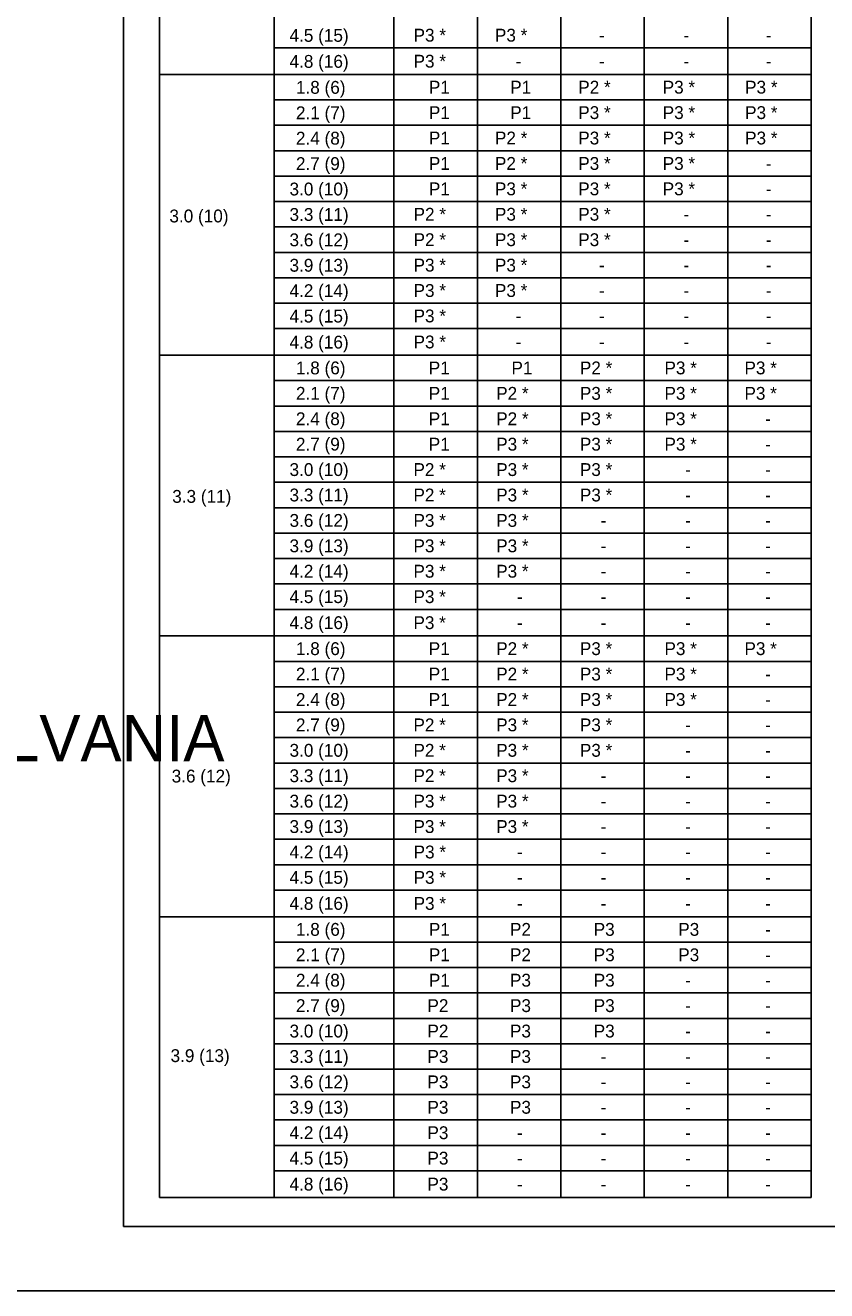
# Model space of a CAD drawing. Extents: x -1958 to 628, y -879 to 309.
# Drawn here: x -1100.4 to -913, y -878.6 to -582.8 of the extents above; entities that cross this region are included whole.
import ezdxf

# ---------------------------------------------------------------- set-up
doc = ezdxf.new("R2010")
doc.units = 0
for name, color, linetype in [('1', 7, 'Continuous'), ('2', 7, 'Continuous'), ('30', 7, 'Continuous'), ('PLT-BNDY', 7, 'Continuous')]:
    doc.layers.add(name, color=color, linetype=linetype)

msp = doc.modelspace()

# ---------------------------------------------------------------- linework, layer by layer
at = {"layer": '1'}
for p, q in [((-1077.39, -299.56), (-1077.39, -863.56)), ((-1069, -856.76), (-1069, -331.88)), ((-916.65, -856.76), (-916.65, -331.88)), ((-1042.2, -665.87), (-916.65, -665.87)), ((-1042.2, -671.81), (-916.65, -671.81)), ((-1042.2, -677.75), (-916.65, -677.75)), ((-1042.2, -683.69), (-916.65, -683.69)), ((-1042.2, -689.63), (-916.65, -689.63)), ((-1042.2, -695.57), (-916.65, -695.57)), ((-1042.2, -701.51), (-916.65, -701.51)), ((-1042.2, -707.45), (-916.65, -707.45)), ((-1042.2, -713.39), (-916.65, -713.39)), ((-1042.2, -719.33), (-916.65, -719.33)), ((-1069, -725.54), (-916.65, -725.54)), ((-1042.2, -731.48), (-916.65, -731.48)), ((-1042.2, -737.42), (-916.65, -737.42)), ((-1042.2, -743.36), (-916.65, -743.36)), ((-1042.2, -749.3), (-916.65, -749.3)), ((-940.21, -749.3), (-916.65, -749.3)), ((-1042.2, -755.24), (-916.65, -755.24)), ((-1042.2, -761.18), (-916.65, -761.18)), ((-1042.2, -767.12), (-916.65, -767.12)), ((-940.21, -767.12), (-916.65, -767.12)), ((-1042.2, -773.06), (-916.65, -773.06)), ((-1042.2, -779), (-916.65, -779)), ((-1042.2, -784.94), (-916.65, -784.94)), ((-1069, -791.15), (-916.65, -791.15)), ((-1042.2, -797.09), (-916.65, -797.09)), ((-1042.2, -803.03), (-916.65, -803.03)), ((-1042.2, -808.97), (-916.65, -808.97)), ((-1042.2, -814.91), (-916.65, -814.91)), ((-1042.2, -820.85), (-916.65, -820.85)), ((-1042.2, -826.79), (-916.65, -826.79)), ((-1042.2, -832.73), (-916.65, -832.73)), ((-1042.2, -838.67), (-916.65, -838.67)), ((-1042.2, -844.61), (-916.65, -844.61)), ((-1042.2, -850.55), (-916.65, -850.55)), ((-1069, -856.76), (-916.65, -856.76)), ((-291.39, -863.56), (-1077.39, -863.56)), ((-1077.39, -863.56), (-491.39, -863.56))]:
    msp.add_line(p, q, dxfattribs=at)
at = {"layer": '2'}
for p, q in [((-1042.2, -856.76), (-1042.2, -331.88)), ((-1014.19, -856.76), (-1014.19, -331.88)), ((-994.68, -856.76), (-994.68, -331.88)), ((-975.17, -856.76), (-975.17, -331.88)), ((-955.67, -856.76), (-955.67, -331.88)), ((-936.16, -856.76), (-936.16, -331.88)), ((-1042.2, -588.11), (-916.65, -588.11)), ((-1069, -594.32), (-916.65, -594.32)), ((-1042.2, -600.26), (-916.65, -600.26)), ((-1042.2, -606.2), (-916.65, -606.2)), ((-1042.2, -612.14), (-916.65, -612.14)), ((-1042.2, -618.08), (-916.65, -618.08)), ((-1042.2, -624.02), (-916.65, -624.02)), ((-1042.2, -629.96), (-916.65, -629.96)), ((-1042.2, -635.9), (-916.65, -635.9)), ((-1042.2, -641.84), (-916.65, -641.84)), ((-1042.2, -647.78), (-916.65, -647.78)), ((-1042.2, -653.72), (-916.65, -653.72)), ((-975.85, -653.72), (-940.21, -653.72)), ((-1069, -659.93), (-916.65, -659.93))]:
    msp.add_line(p, q, dxfattribs=at)
at = {"layer": 'PLT-BNDY'}
msp.add_lwpolyline([(-1117.39, -284.56), (-276.39, -284.56), (-276.39, -878.56), (-1117.39, -878.56)], close=True, dxfattribs=at)

# ---------------------------------------------------------------- texts
at = {"layer": '1'}
for s, height, p in [('2.1 (7)', 3, (-1037.1, -670.34)), ('P1', 3, (-1006.05, -670.34)), ('P2 *', 3, (-990.29, -670.34)), ('P3 *', 3, (-970.72, -670.34)), ('P3 *', 3, (-950.95, -670.34)), ('P3 *', 3, (-932.25, -670.34)), ('2.4 (8)', 3, (-1037.1, -676.28)), ('P1', 3, (-1006.05, -676.28)), ('P2 *', 3, (-990.29, -676.28)), ('P3 *', 3, (-970.72, -676.28)), ('P3 *', 3, (-950.95, -676.28)), ('-', 3, (-927.4, -676.28)), ('2.7 (9)', 3, (-1037.1, -682.22)), ('P1', 3, (-1006.05, -682.22)), ('P3 *', 3, (-990.29, -682.22)), ('P3 *', 3, (-970.72, -682.22)), ('P3 *', 3, (-950.95, -682.22)), ('-', 3, (-927.4, -682.22)), ('3.0 (10)', 3, (-1038.6, -688.16)), ('P2 *', 3, (-1009.63, -688.16)), ('P3 *', 3, (-990.29, -688.16)), ('P3 *', 3, (-970.72, -688.16)), ('-', 3, (-946.1, -688.16)), ('-', 3, (-927.4, -688.16)), ('3.3 (11)', 3, (-1038.6, -694.1)), ('P2 *', 3, (-1009.63, -694.1)), ('P3 *', 3, (-990.29, -694.1)), ('P3 *', 3, (-970.72, -694.1)), ('-', 3, (-946.1, -694.1)), ('-', 3, (-927.4, -694.1)), ('3.6 (12)', 3, (-1038.6, -700.04)), ('P3 *', 3, (-1009.63, -700.04)), ('P3 *', 3, (-990.29, -700.04)), ('-', 3, (-965.87, -700.04)), ('-', 3, (-946.1, -700.04)), ('-', 3, (-927.4, -700.04)), ('3.9 (13)', 3, (-1038.6, -705.98)), ('P3 *', 3, (-1009.63, -705.98)), ('P3 *', 3, (-990.29, -705.98)), ('-', 3, (-965.87, -705.98)), ('-', 3, (-946.1, -705.98)), ('-', 3, (-927.4, -705.98)), ('4.2 (14)', 3, (-1038.6, -711.92)), ('P3 *', 3, (-1009.63, -711.92)), ('P3 *', 3, (-990.29, -711.92)), ('-', 3, (-965.87, -711.92)), ('-', 3, (-946.1, -711.92)), ('-', 3, (-927.4, -711.92)), ('4.5 (15)', 3, (-1038.6, -717.86)), ('P3 *', 3, (-1009.63, -717.86)), ('-', 3, (-985.44, -717.86)), ('-', 3, (-965.87, -717.86)), ('-', 3, (-946.1, -717.86)), ('-', 3, (-927.4, -717.86)), ('4.8 (16)', 3, (-1038.6, -723.94)), ('P3 *', 3, (-1009.63, -723.94)), ('-', 3, (-985.44, -723.94)), ('-', 3, (-965.87, -723.94)), ('-', 3, (-946.1, -723.94)), ('-', 3, (-927.4, -723.94)), ('1.8 (6)', 3, (-1037.1, -730.01)), ('P1', 3, (-1006.05, -730.01)), ('P2 *', 3, (-990.29, -730.01)), ('P3 *', 3, (-970.72, -730.01)), ('P3 *', 3, (-950.95, -730.01)), ('P3 *', 3, (-932.25, -730.01)), ('2.1 (7)', 3, (-1037.1, -735.95)), ('P1', 3, (-1006.05, -735.95)), ('P2 *', 3, (-990.29, -735.95)), ('P3 *', 3, (-970.72, -735.95)), ('P3 *', 3, (-950.95, -735.95)), ('-', 3, (-927.4, -735.95)), ('2.4 (8)', 3, (-1037.1, -741.89)), ('P1', 3, (-1006.05, -741.89)), ('P2 *', 3, (-990.29, -741.89)), ('P3 *', 3, (-970.72, -741.89)), ('P3 *', 3, (-950.95, -741.89)), ('-', 3, (-927.4, -741.89)), ('COMMONWEALTH OF PENNSYLVANIA', 10.7827, (-1319.79, -754.83)), ('2.7 (9)', 3, (-1037.1, -747.83)), ('P2 *', 3, (-1009.63, -747.83)), ('P3 *', 3, (-990.29, -747.83)), ('P3 *', 3, (-970.72, -747.83)), ('-', 3, (-946.1, -747.83)), ('-', 3, (-927.4, -747.83)), ('3.0 (10)', 3, (-1038.6, -753.77)), ('P2 *', 3, (-1009.63, -753.77)), ('P3 *', 3, (-990.29, -753.77)), ('P3 *', 3, (-970.72, -753.77)), ('-', 3, (-946.1, -753.77)), ('-', 3, (-927.4, -753.77)), ('3.6 (12)', 3, (-1066.15, -759.79)), ('3.3 (11)', 3, (-1038.6, -759.71)), ('P2 *', 3, (-1009.63, -759.71)), ('P3 *', 3, (-990.29, -759.71)), ('-', 3, (-965.87, -759.71)), ('-', 3, (-946.1, -759.71)), ('-', 3, (-927.4, -759.71)), ('3.6 (12)', 3, (-1038.6, -765.65)), ('P3 *', 3, (-1009.63, -765.65)), ('P3 *', 3, (-990.29, -765.65)), ('-', 3, (-965.87, -765.65)), ('-', 3, (-946.1, -765.65)), ('-', 3, (-927.4, -765.65)), ('3.9 (13)', 3, (-1038.6, -771.59)), ('P3 *', 3, (-1009.63, -771.59)), ('P3 *', 3, (-990.29, -771.59)), ('-', 3, (-965.87, -771.59)), ('-', 3, (-946.1, -771.59)), ('-', 3, (-927.4, -771.59)), ('4.2 (14)', 3, (-1038.6, -777.53)), ('P3 *', 3, (-1009.59, -777.53)), ('-', 3, (-985.44, -777.53)), ('-', 3, (-965.87, -777.53)), ('-', 3, (-946.1, -777.53)), ('-', 3, (-927.4, -777.53)), ('4.5 (15)', 3, (-1038.6, -783.47)), ('P3 *', 3, (-1009.59, -783.47)), ('-', 3, (-985.44, -783.47)), ('-', 3, (-965.87, -783.47)), ('-', 3, (-946.1, -783.47)), ('-', 3, (-927.4, -783.47)), ('4.8 (16)', 3, (-1038.6, -789.55)), ('P3 *', 3, (-1009.59, -789.55)), ('-', 3, (-985.44, -789.55)), ('-', 3, (-965.87, -789.55)), ('-', 3, (-946.1, -789.55)), ('-', 3, (-927.4, -789.55)), ('1.8 (6)', 3, (-1037.1, -795.62)), ('P1', 3, (-1006.02, -795.62)), ('P2', 3, (-987.06, -795.62)), ('P3', 3, (-967.49, -795.62)), ('P3', 3, (-947.72, -795.62)), ('-', 3, (-927.4, -795.62)), ('2.1 (7)', 3, (-1037.1, -801.56)), ('P1', 3, (-1006.02, -801.56)), ('P2', 3, (-987.06, -801.56)), ('P3', 3, (-967.49, -801.56)), ('P3', 3, (-947.72, -801.56)), ('-', 3, (-927.4, -801.56)), ('2.4 (8)', 3, (-1037.1, -807.5)), ('P1', 3, (-1006.02, -807.5)), ('P3', 3, (-987.06, -807.5)), ('P3', 3, (-967.49, -807.5)), ('-', 3, (-946.1, -807.5)), ('-', 3, (-927.4, -807.5)), ('2.7 (9)', 3, (-1037.1, -813.44)), ('P2', 3, (-1006.36, -813.44)), ('P3', 3, (-987.06, -813.44)), ('P3', 3, (-967.49, -813.44)), ('-', 3, (-946.1, -813.44)), ('-', 3, (-927.4, -813.44)), ('3.0 (10)', 3, (-1038.6, -819.38)), ('P2', 3, (-1006.36, -819.38)), ('P3', 3, (-987.06, -819.38)), ('P3', 3, (-967.49, -819.38)), ('-', 3, (-946.1, -819.38)), ('-', 3, (-927.4, -819.38)), ('3.9 (13)', 3, (-1066.41, -825.13)), ('3.3 (11)', 3, (-1038.6, -825.32)), ('P3', 3, (-1006.36, -825.32)), ('P3', 3, (-987.06, -825.32)), ('-', 3, (-965.87, -825.32)), ('-', 3, (-946.1, -825.32)), ('-', 3, (-927.4, -825.32)), ('3.6 (12)', 3, (-1038.6, -831.26)), ('P3', 3, (-1006.36, -831.26)), ('P3', 3, (-987.06, -831.26)), ('-', 3, (-965.87, -831.26)), ('-', 3, (-946.1, -831.26)), ('-', 3, (-927.4, -831.26)), ('3.9 (13)', 3, (-1038.6, -837.2)), ('P3', 3, (-1006.36, -837.2)), ('P3', 3, (-987.06, -837.2)), ('-', 3, (-965.88, -837.2)), ('-', 3, (-946.1, -837.2)), ('-', 3, (-927.4, -837.2)), ('4.2 (14)', 3, (-1038.6, -843.14)), ('P3', 3, (-1006.36, -843.14)), ('-', 3, (-985.44, -843.14)), ('-', 3, (-965.88, -843.14)), ('-', 3, (-946.1, -843.14)), ('-', 3, (-927.4, -843.14)), ('4.5 (15)', 3, (-1038.6, -849.08)), ('P3', 3, (-1006.36, -849.08)), ('-', 3, (-985.44, -849.08)), ('-', 3, (-965.88, -849.08)), ('-', 3, (-946.1, -849.08)), ('-', 3, (-927.4, -849.08)), ('4.8 (16)', 3, (-1038.6, -855.16)), ('P3', 3, (-1006.36, -855.16)), ('-', 3, (-985.44, -855.16)), ('-', 3, (-965.88, -855.16)), ('-', 3, (-946.1, -855.16)), ('-', 3, (-927.4, -855.16))]:
    msp.add_text(s, height=height, dxfattribs=at).set_placement(p)
at = {"layer": '2'}
for s, p in [('4.5 (15)', (-1038.6, -586.68)), ('P3 *', (-1009.6, -586.64)), ('P3 *', (-990.58, -586.64)), ('-', (-966.25, -586.64)), ('-', (-946.51, -586.64)), ('-', (-927.25, -586.64)), ('4.8 (16)', (-1038.6, -592.76)), ('P3 *', (-1009.6, -592.72)), ('-', (-985.73, -592.72)), ('-', (-966.25, -592.72)), ('-', (-946.51, -592.72)), ('-', (-927.25, -592.72)), ('1.8 (6)', (-1037.1, -598.83)), ('P1', (-1006.02, -598.79)), ('P1', (-987.01, -598.79)), ('P2 *', (-971.1, -598.79)), ('P3 *', (-951.36, -598.79)), ('P3 *', (-932.1, -598.79)), ('2.1 (7)', (-1037.1, -604.77)), ('P1', (-1006.02, -604.73)), ('P1', (-987.01, -604.73)), ('P3 *', (-971.1, -604.73)), ('P3 *', (-951.36, -604.73)), ('P3 *', (-932.1, -604.73)), ('2.4 (8)', (-1037.1, -610.71)), ('P1', (-1006.02, -610.67)), ('P2 *', (-990.58, -610.67)), ('P3 *', (-971.1, -610.67)), ('P3 *', (-951.36, -610.67)), ('P3 *', (-932.1, -610.67)), ('2.7 (9)', (-1037.1, -616.65)), ('P1', (-1006.02, -616.61)), ('P2 *', (-990.58, -616.61)), ('P3 *', (-971.1, -616.61)), ('P3 *', (-951.36, -616.61)), ('-', (-927.25, -616.61)), ('3.0 (10)', (-1038.6, -622.59)), ('P1', (-1006.02, -622.55)), ('P3 *', (-990.58, -622.55)), ('P3 *', (-971.1, -622.55)), ('P3 *', (-951.36, -622.55)), ('-', (-927.25, -622.55)), ('3.0 (10)', (-1066.68, -628.89)), ('3.3 (11)', (-1038.6, -628.53)), ('P2 *', (-1009.6, -628.49)), ('P3 *', (-990.58, -628.49)), ('P3 *', (-971.1, -628.49)), ('-', (-946.51, -628.49)), ('-', (-927.25, -628.49)), ('3.6 (12)', (-1038.6, -634.47)), ('P2 *', (-1009.6, -634.43)), ('P3 *', (-990.58, -634.43)), ('P3 *', (-971.1, -634.43)), ('-', (-946.51, -634.43)), ('-', (-927.25, -634.43)), ('3.9 (13)', (-1038.6, -640.41)), ('P3 *', (-1009.6, -640.37)), ('P3 *', (-990.58, -640.37)), ('-', (-966.25, -640.37)), ('-', (-946.51, -640.37)), ('-', (-927.25, -640.37)), ('4.2 (14)', (-1038.6, -646.35)), ('P3 *', (-1009.6, -646.31)), ('P3 *', (-990.58, -646.31)), ('-', (-966.25, -646.31)), ('-', (-946.51, -646.31)), ('-', (-927.25, -646.31)), ('4.5 (15)', (-1038.6, -652.29)), ('P3 *', (-1009.6, -652.25)), ('-', (-985.73, -652.25)), ('-', (-966.25, -652.25)), ('-', (-946.51, -652.25)), ('-', (-927.25, -652.25)), ('4.8 (16)', (-1038.6, -658.37)), ('P3 *', (-1009.6, -658.33)), ('-', (-985.73, -658.33)), ('-', (-966.25, -658.33)), ('-', (-946.51, -658.33)), ('-', (-927.25, -658.33))]:
    msp.add_text(s, height=3, dxfattribs=at).set_placement(p)
at = {"layer": '30'}
for s, p in [('1.8 (6)', (-1037.1, -664.4)), ('P1', (-1006.05, -664.4)), ('P1', (-986.72, -664.4)), ('P2 *', (-970.72, -664.4)), ('P3 *', (-950.95, -664.4)), ('P3 *', (-932.25, -664.4)), ('3.3 (11)', (-1066.02, -694.42))]:
    msp.add_text(s, height=3, dxfattribs=at).set_placement(p)

doc.saveas('drawing.dxf')
